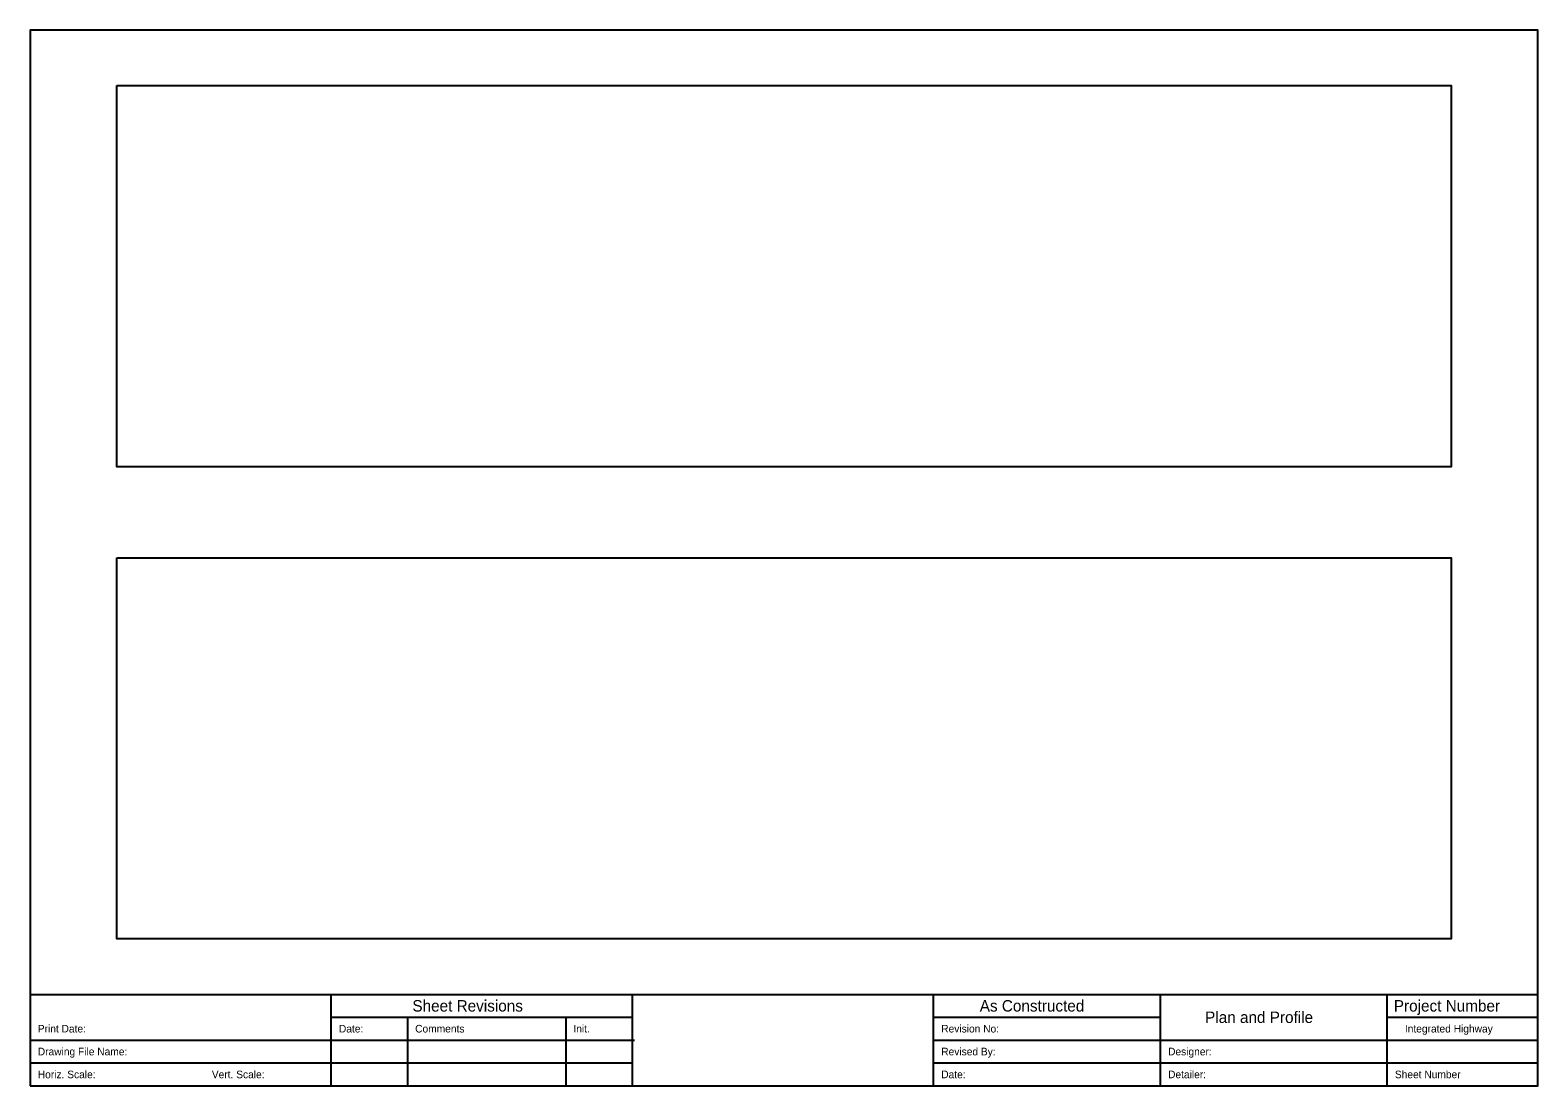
# Model space of a CAD drawing. Extents: x 0.03 to 0.821, y 0.02 to 0.574.
import ezdxf

# ---------------------------------------------------------------- set-up
doc = ezdxf.new("R2010")
doc.units = 0
doc.layers.add('Constructions', color=7, linetype='Continuous')
doc.layers.add('Draft_Sheet', color=7, linetype='Continuous')

msp = doc.modelspace()

# ---------------------------------------------------------------- linework, layer by layer
at = {"layer": 'Constructions'}
for points in [[(0.0755, 0.54489), (0.7755, 0.54489), (0.7755, 0.34489), (0.0755, 0.34489)], [(0.0755, 0.29711), (0.7755, 0.29711), (0.7755, 0.09711), (0.0755, 0.09711)]]:
    msp.add_lwpolyline(points, close=True, dxfattribs=at)
at = {"layer": 'Draft_Sheet'}
for p, q in [((0.03, 0.068), (0.821, 0.068)), ((0.188, 0.02), (0.188, 0.068)), ((0.346, 0.02), (0.346, 0.068)), ((0.504, 0.02), (0.504, 0.068)), ((0.623, 0.02), (0.623, 0.068)), ((0.742, 0.02), (0.742, 0.068)), ((0.188, 0.056), (0.346, 0.056)), ((0.228, 0.056), (0.228, 0.02)), ((0.311, 0.056), (0.311, 0.02)), ((0.504, 0.056), (0.623, 0.056)), ((0.742, 0.056), (0.821, 0.056)), ((0.03, 0.044), (0.347, 0.044)), ((0.504, 0.044), (0.821, 0.044)), ((0.03, 0.032), (0.346, 0.032)), ((0.504, 0.032), (0.821, 0.032))]:
    msp.add_line(p, q, dxfattribs=at)
msp.add_lwpolyline([(0.03, 0.02), (0.821, 0.02), (0.821, 0.574), (0.03, 0.574)], close=True, dxfattribs=at)

# ---------------------------------------------------------------- texts
for s, height, p in [('Sheet Revisions', 0.006, (0.23054, 0.059)), ('As Constructed', 0.006, (0.5282, 0.059)), ('Project Number', 0.006, (0.74544, 0.059)), ('Plan and Profile', 0.006, (0.64644, 0.053)), ('Print Date:', 0.004, (0.034, 0.048)), ('Date:', 0.004, (0.192, 0.048)), ('Comments', 0.004, (0.232, 0.048)), ('Init.', 0.004, (0.315, 0.048)), ('Revision No:', 0.004, (0.508, 0.048)), ('Integrated Highway', 0.004, (0.75126, 0.048)), ('Drawing File Name:', 0.004, (0.034, 0.036)), ('Revised By:', 0.004, (0.508, 0.036)), ('Designer:', 0.004, (0.627, 0.036)), ('Horiz. Scale:', 0.004, (0.034, 0.024)), ('Vert. Scale:', 0.004, (0.12532, 0.024)), ('Date:', 0.004, (0.508, 0.024)), ('Detailer:', 0.004, (0.627, 0.024)), ('Sheet Number', 0.004, (0.746, 0.024))]:
    msp.add_text(s, height=height, dxfattribs=at).set_placement(p)

doc.saveas('drawing.dxf')
